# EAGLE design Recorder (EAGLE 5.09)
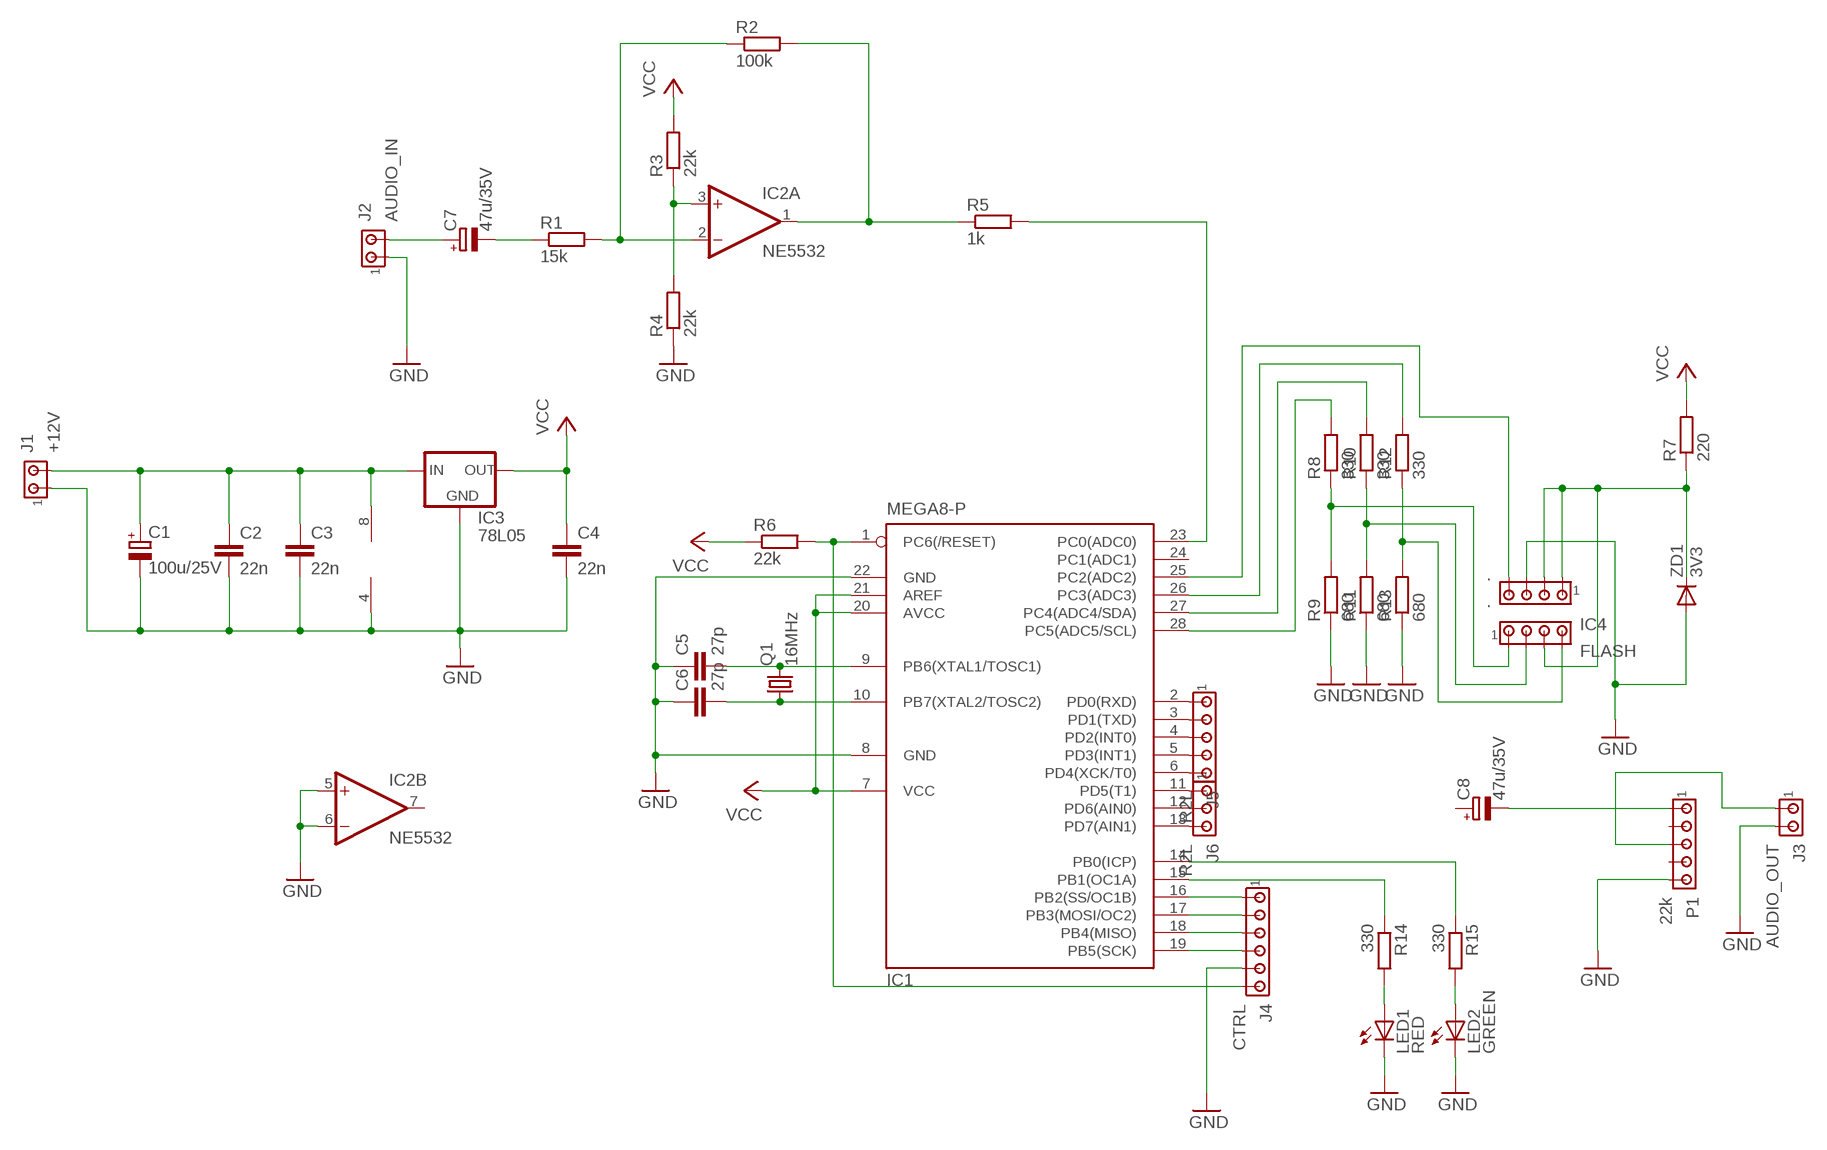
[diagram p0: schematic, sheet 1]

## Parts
.  .  MTA04-100  [10X04MTA]
C1  100u/25V  CPOL-EUE5-5  [E5-5]
C2  22n  C-EU025-024X044  [C025-024X044]
C3  22n  C-EU025-024X044  [C025-024X044]
C4  22n  C-EU025-024X044  [C025-024X044]
C5  27p  C-EU050-024X044  [C050-024X044]
C6  27p  C-EU050-024X044  [C050-024X044]
C7  47u/35V  CPOL-EUE2.5-5  [E2,5-5]
C8  47u/35V  CPOL-EUE2.5-5  [E2,5-5]
IC1  MEGA8-P  [DIL28-3]
IC2  NE5532  LM1458N  [DIL08]
IC3  78L05  78XXS  [78XXS]
IC4  FLASH  MTA04-100  [10X04MTA]
J1  +12V  MTA02-100  [10X02MTA]
J2  AUDIO_IN  MTA02-100  [10X02MTA]
J3  AUDIO_OUT  MTA02-100  [10X02MTA]
J4  CTRL  MTA06-100  [10X06MTA]
J5  R2L  MTA05-100  [10X05MTA]
J6  R2L  MTA03-100  [10X03MTA]
LED1  RED  LED5MM  [LED5MM]
LED2  GREEN  LED5MM  [LED5MM]
P1  22k  MTA05-100  [10X05MTA]
Q1  16MHz  CRYSTALHC49U-V  [HC49U-V]
R1  15k  R-EU_0207/10  [0207/10]
R2  100k  R-EU_0207/10  [0207/10]
R3  22k  R-EU_0207/10  [0207/10]
R4  22k  R-EU_0207/10  [0207/10]
R5  1k  R-EU_0207/2V  [0207/2V]
R6  22k  R-EU_0207/10  [0207/10]
R7  220  R-EU_0207/10  [0207/10]
R8  330  R-EU_0207/10  [0207/10]
R9  680  R-EU_0207/10  [0207/10]
R10  330  R-EU_0207/10  [0207/10]
R11  680  R-EU_0207/10  [0207/10]
R12  330  R-EU_0207/10  [0207/10]
R13  680  R-EU_0207/10  [0207/10]
R14  330  R-EU_0207/10  [0207/10]
R15  330  R-EU_0207/10  [0207/10]
ZD1  3V3  1N4148DO35-7  [DO35-7]

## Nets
GND: ..3 C1.- C2.2 C3.2 C4.2 C5.1 C6.1 IC1.8(GND) IC1.22(GND) IC2.4(P:V-) IC2.5(B:+IN) IC2.6(B:-IN) IC3.GND J1.1 J2.1 J3.2 J4.2 LED1.K(C) LED2.K(C) P1.5 R4.1 R9.1 R11.1 R13.1 ZD1.A
N$1: IC1.2(PD0(RXD)) J5.1
N$2: IC1.3(PD1(TXD)) J5.2
N$3: IC1.4(PD2(INT0)) J5.3
N$4: IC1.5(PD3(INT1)) J5.4
N$5: IC1.6(PD4(XCK/T0)) J5.5
N$6: IC1.11(PD5(T1)) J6.1
N$7: IC1.13(PD7(AIN1)) J6.3
N$8: IC1.12(PD6(AIN0)) J6.2
N$9: C5.2 IC1.9(PB6(XTAL1/TOSC1)) Q1.2
N$10: C6.2 IC1.10(PB7(XTAL2/TOSC2)) Q1.1
N$11: IC1.1(PC6(/RESET)) J4.1 R6.2
N$12: C8.- P1.1
N$13: J3.1 P1.3
N$14: IC2.2(A:-IN) R1.2 R2.1
N$15: IC1.23(PC0(ADC0)) R5.2
N$16: C7.- R1.1
N$17: C7.+ J2.2
N$18: IC2.3(A:+IN) R3.1 R4.2
N$19: IC2.1(A:OUT) R2.2 R5.1
N$20: LED1.A R14.2
N$21: LED2.A R15.2
N$22: IC1.15(PB1(OC1A)) R14.1
N$23: IC1.28(PC5(ADC5/SCL)) R8.2
N$24: IC1.14(PB0(ICP)) R15.1
N$25: IC4.1 R8.1 R9.2
N$27: ..1 ..2 IC4.3 R7.1 ZD1.C
N$28: IC4.2 R10.1 R11.2
N$29: IC1.17(PB3(MOSI/OC2)) J4.5
N$30: IC4.4 R12.1 R13.2
N$31: IC1.18(PB4(MISO)) J4.4
N$32: IC1.19(PB5(SCK)) J4.3
N$33: IC1.27(PC4(ADC4/SDA)) R10.2
N$34: IC1.16(PB2(SS/OC1B)) J4.6
N$35: ..4 IC1.25(PC2(ADC2))
N$36: C1.+ C2.1 C3.1 IC2.8(P:V+) IC3.IN J1.2
N$37: IC1.26(PC3(ADC3)) R12.2
VCC: C4.1 IC1.7(VCC) IC1.20(AVCC) IC1.21(AREF) IC3.OUT R3.2 R6.1 R7.2
Unconnected: C8.+ IC1.24(PC1(ADC1)) IC2.7(B:OUT) P1.2 P1.4

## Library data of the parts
. IC4 = con-amp:MTA04-100: AMP connector
C1 C7 C8 = rcl:CPOL-EU: POLARIZED CAPACITOR, European symbol
C2-C6 = rcl:C-EU: CAPACITOR, European symbol
IC1 = atmel:MEGA8-P: MICROCONTROLLER 8 Kbytes FLASH, 1 kbytes SRAM, 512 bytes EEPROM, USART, 4-channel 10 bit ADC, 2-channel 8 bit ADC Pin compatible with Atmega48, ATMega88, ATMega168 Source: avr.lbr
IC2 = linear:*1458: OP AMP
IC3 = v-reg:78XXS: VOLTAGE REGULATOR
J1-J3 = con-amp:MTA02-100: AMP connector
J4 = con-amp:MTA06-100: AMP connector
J5 P1 = con-amp:MTA05-100: AMP connector
J6 = con-amp:MTA03-100: AMP connector
LED1 LED2 = led:LED: LED
Q1 = crystal:CRYSTAL: CRYSTAL
R1-R15 = rcl:R-EU_: RESISTOR, European symbol
ZD1 = diode:1N4148: DIODE

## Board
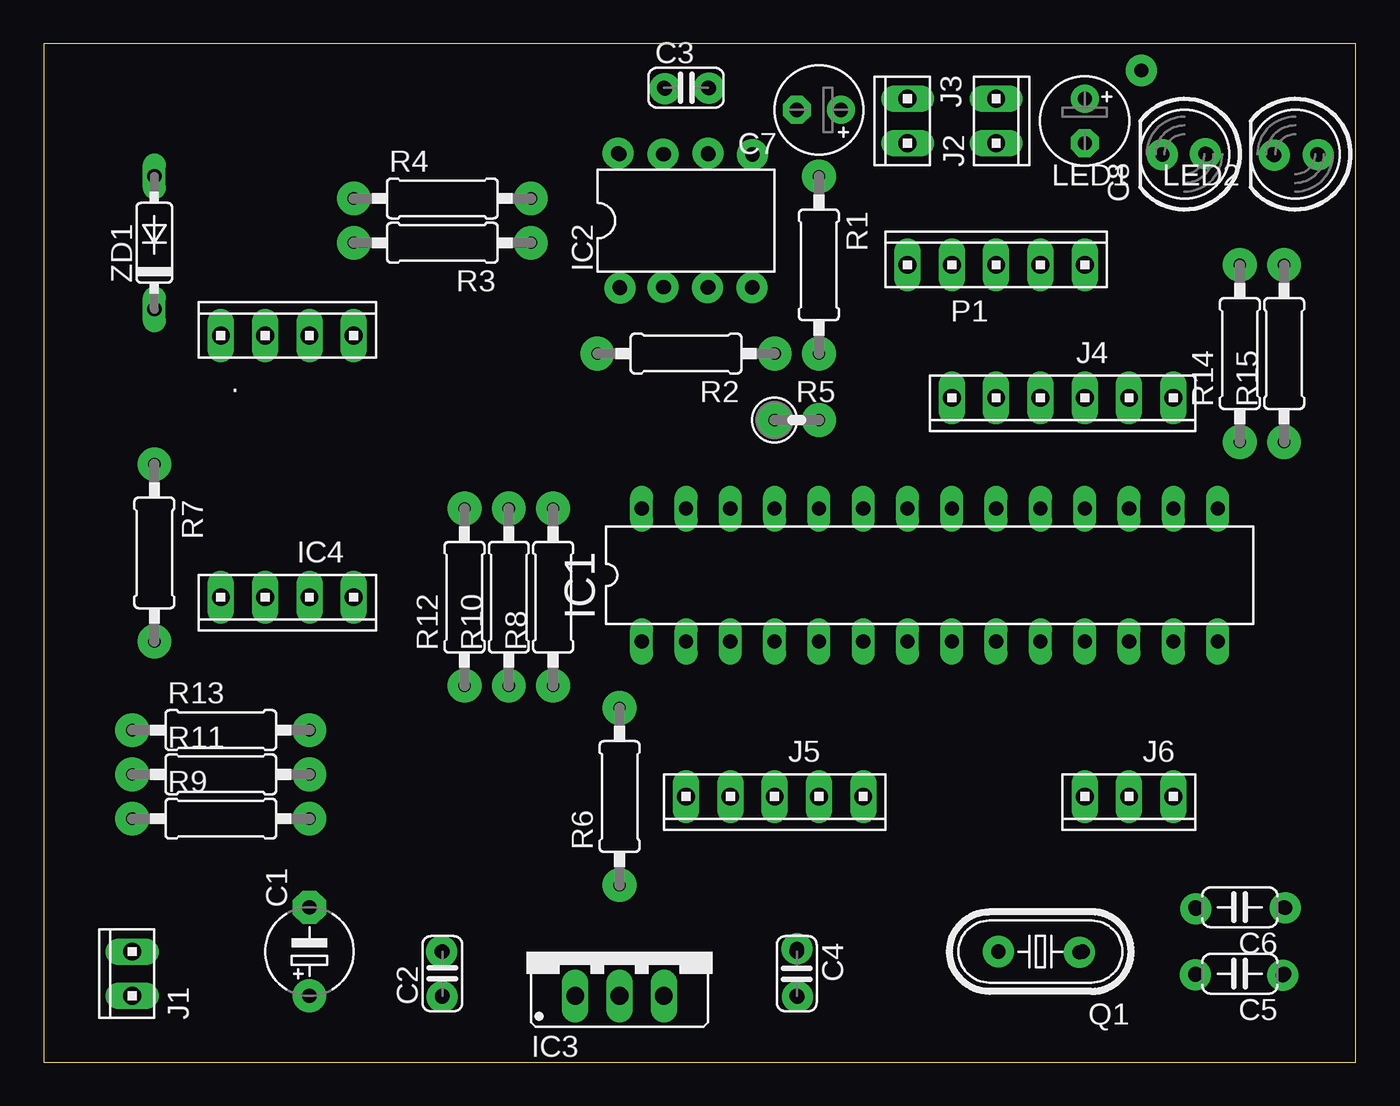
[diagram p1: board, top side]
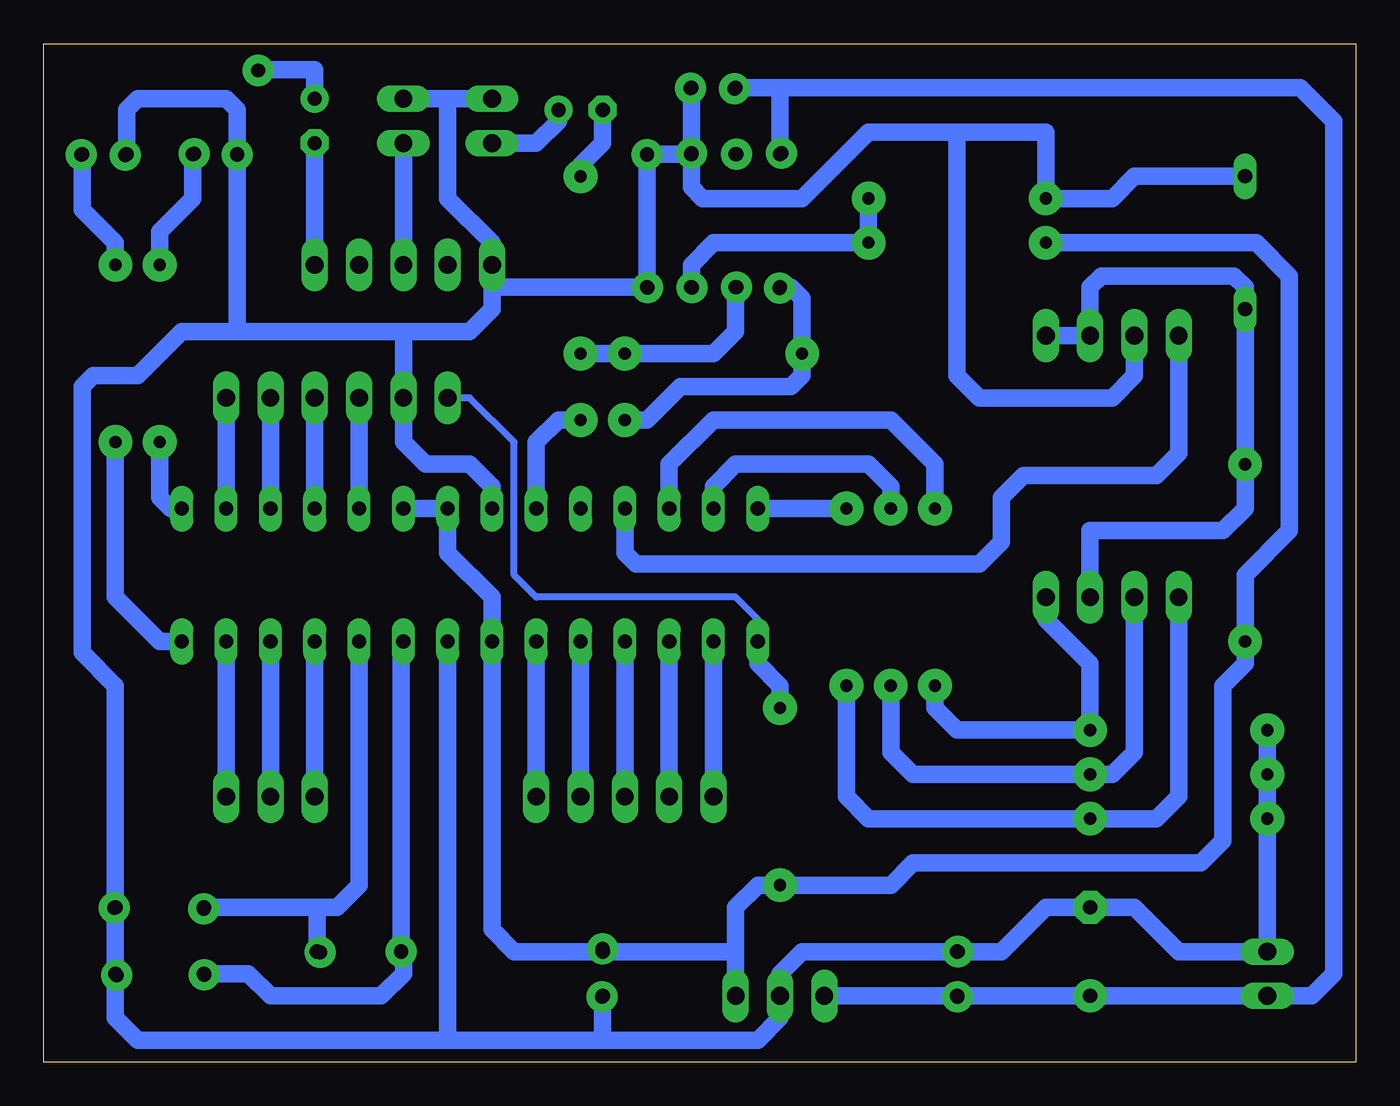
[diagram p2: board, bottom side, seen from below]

Size 75.23 x 58.41 mm. Coordinates in mm from the lower left corner, seen from the top.
Outline: 0,0 75.23,0 75.23,58.41 0,58.41 0,0
Copper layers (1*16): Top 0.035mm / dielectric 1.5mm / Bottom 0.035mm
Design rules "default": minimum track width 10mil, minimum drill 24mil, track to track 8mil, track to pad 8mil, pad to pad 8mil, via to via 8mil, smd to smd 8mil, copper to edge 40mil, drill to drill 8mil, minimum pad ring 10mil, minimum via ring 8mil, stop-mask expansion 4mil, vias tented up to drill 0mil, thermal gap 10mil

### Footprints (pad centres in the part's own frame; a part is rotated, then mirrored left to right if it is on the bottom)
10X04MTA = drill 1.016 long: 1 3.81,0; 2 1.27,0; 3 -1.27,0; 4 -3.81,0
E5-5 = drill 0.813 pad 1.905 round: + -2.54,0 | drill 0.813 pad 1.905 octagon: - 2.54,0
C025-024X044 = drill 0.813 octagon: 1 -1.27,0; 2 1.27,0
C050-024X044 = drill 0.813 octagon: 1 -2.54,0; 2 2.54,0
E2,5-5 = drill 0.813 pad 1.6 round: + -1.27,0 | drill 0.813 pad 1.6 octagon: - 1.27,0
DIL28-3 = drill 0.813 long: 1 -16.51,-3.81; 2 -13.97,-3.81; 3 -11.43,-3.81; 4 -8.89,-3.81; 5 -6.35,-3.81; 6 -3.81,-3.81; 7 -1.27,-3.81; 8 1.27,-3.81; 9 3.81,-3.81; 10 6.35,-3.81; 11 8.89,-3.81; 12 11.43,-3.81; 13 13.97,-3.81; 14 16.51,-3.81; 15 16.51,3.81; 16 13.97,3.81; 17 11.43,3.81; 18 8.89,3.81; 19 6.35,3.81; 20 3.81,3.81; 21 1.27,3.81; 22 -1.27,3.81; 23 -3.81,3.81; 24 -6.35,3.81; 25 -8.89,3.81; 26 -11.43,3.81; 27 -13.97,3.81; 28 -16.51,3.81
DIL08 = drill 0.813 pad 1.27 round: 1 -3.81,-3.81; 2 -1.27,-3.81; 3 1.27,-3.81; 4 3.81,-3.81; 5 3.81,3.81; 6 1.27,3.81; 7 -1.27,3.81; 8 -3.81,3.81
78XXS = drill 1.016 long: GND 0,-2.54; IN -2.54,-2.54; OUT 2.54,-2.54
10X02MTA = drill 1.016 long: 1 1.27,0; 2 -1.27,0
10X06MTA = drill 1.016 long: 1 6.35,0; 2 3.81,0; 3 1.27,0; 4 -1.27,0; 5 -3.81,0; 6 -6.35,0
10X05MTA = drill 1.016 long: 1 5.08,0; 2 2.54,0; 3 0,0; 4 -2.54,0; 5 -5.08,0
10X03MTA = drill 1.016 long: 1 2.54,0; 2 0,0; 3 -2.54,0
LED5MM = drill 0.813 octagon: A -1.27,0; K 1.27,0
HC49U-V = drill 0.813 round: 1 -2.413,0; 2 2.413,0
0207/10 = drill 0.7 pad 1.93 round: 1 -5.08,0; 2 5.08,0
0207/2V = drill 0.7 pad 1.93 round: 1 -1.27,0; 2 1.27,0
DO35-7 = drill 0.813 long: A 3.81,0; C -3.81,0

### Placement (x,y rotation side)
.  13.97,41.67 0 top
C1  15.24,6.35 90 top
C2  22.86,5.08 90 top
C3  36.83,55.88 0 top
C4  43.18,5.08 270 top
C5  68.58,5.08 180 top
C6  68.58,8.89 180 top
C7  44.45,54.61 180 top
C8  59.69,53.98 270 top
IC1  50.8,27.94 0 top
IC2  36.83,48.26 0 top
IC3  33.02,6.35 0 top
IC4  13.97,26.67 180 top
J1  5.08,5.08 90 top
J2  49.53,53.98 90 top
J3  54.61,53.98 270 top
J4  58.42,38.1 180 top
J5  41.91,15.24 180 top
J6  62.23,15.24 180 top
LED1  65.41,52.07 180 top
LED2  71.75,52.07 180 top
P1  54.61,45.72 0 top
Q1  57.15,6.35 180 top
R1  44.45,45.72 270 top
R2  36.83,40.64 180 top
R3  22.86,46.99 180 top
R4  22.86,49.53 0 top
R5  43.18,36.83 0 top
R6  33.02,15.24 90 top
R7  6.35,29.21 270 top
R8  29.21,26.67 90 top
R9  10.16,13.97 0 top
R10  26.67,26.67 90 top
R11  10.16,16.51 0 top
R12  24.13,26.67 90 top
R13  10.16,19.05 0 top
R14  68.58,40.64 90 top
R15  71.12,40.64 90 top
ZD1  6.35,46.99 90 top

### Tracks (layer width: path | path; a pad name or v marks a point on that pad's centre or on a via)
GND  (via drill 0.8 pad 1.78)
  Bottom 1.016: 43.18,1.27 34.29,1.27 33.02,2.54 IC3.GND 33.02,5.08 31.75,6.35 C2.2 v22.81,6.35 20.32,6.35 17.78,8.89 C1.- 12.7,8.89 10.16,6.35 J1.1 R9.1 R11.1 R13.1 | 43.18,1.27 52.07,1.27 | 52.07,1.27 IC1.8 | 43.18,1.27 C4.2 | IC1.22 49.53,33.02 50.8,34.29 53.34,34.29 54.61,35.56 J4.2 54.61,41.91 | 52.07,1.27 69.85,1.27 71.12,2.54 C5.1 C6.1 71.12,21.59 73.03,23.49 73.03,38.73 72.39,39.37 69.85,39.37 67.31,41.91 64.14,41.91 | IC2.6 IC2.5 IC2.4 49.53,44.45 | IC2.6 C3.2 | 22.86,53.34 17.78,53.34 R4.1 13.97,49.53 12.7,50.8 ZD1.A | 22.86,53.34 27.94,53.34 31.75,49.53 37.47,49.53 38.1,50.16 IC2.6 | ..3 12.7,39.37 13.97,38.1 21.59,38.1 22.86,39.37 22.86,53.34 | 52.07,55.24 J2.1 | 52.07,55.24 J3.2 | 52.07,55.24 52.07,49.53 49.53,46.99 P1.5 49.53,44.45 | 54.61,41.91 50.8,41.91 49.53,43.18 49.53,44.45 | 64.14,41.91 54.61,41.91 | LED2.K 70.48,54.61 69.85,55.24 64.77,55.24 64.14,54.61 LED1.K 64.14,41.91
N$1
  Bottom 1.016: J5.1 IC1.2
N$2
  Bottom 1.016: IC1.3 J5.2
N$3
  Bottom 1.016: J5.3 IC1.4
N$4
  Bottom 1.016: IC1.5 J5.4
N$5
  Bottom 1.016: J5.5 IC1.6
N$6
  Bottom 1.016: IC1.11 J6.1
N$7
  Bottom 1.016: IC1.13 J6.3
N$8
  Bottom 1.016: J6.2 IC1.12
N$9
  Bottom 1.016: C5.2 63.5,5.08 62.23,3.81 55.88,3.81 54.61,5.08 54.61,6.22 Q1.2 54.74,24 IC1.9
N$10
  Bottom 1.016: 59.69,8.89 58.42,8.89 57.15,10.16 IC1.10 | 59.69,8.89 C6.2 | Q1.1 59.56,8.76 59.69,8.89
N$11
  Bottom 0.406: IC1.1 34.29,25.4 35.56,26.67 46.99,26.67 48.26,27.94 48.26,35.56 50.8,38.1 J4.1
  Bottom 1.016: IC1.1 34.29,22.86 33.02,21.59 R6.2
N$12
  Bottom 1.016: P1.1 C8.-
N$13
  Bottom 1.016: J3.1 P1.3
N$14
  Bottom 1.016: R1.2 R2.1 36.83,40.64 35.56,41.91 IC2.2
N$15
  Bottom 1.016: R5.2 45.72,36.83 46.99,35.56 IC1.23
N$16
  Bottom 1.016: C7.- 43.18,52.7 44.45,51.43 R1.1
N$17
  Bottom 1.016: C7.+ 45.72,53.98 46.99,52.7 J2.2
N$18
  Bottom 1.016: R4.2 R3.1 36.83,46.99 38.1,45.72 IC2.3
N$19
  Bottom 1.016: R5.1 40.64,36.83 38.73,38.73 32.38,38.73 31.75,39.37 R2.2 31.75,43.81 32.38,44.45 IC2.1
N$20
  Bottom 1.016: R14.2 68.58,47.62 66.67,49.53 LED1.A
N$21
  Bottom 1.016: R15.2 71.12,46.99 73.03,48.9 LED2.A
N$22
  Bottom 1.016: IC1.15 67.94,31.75 68.58,32.38 R14.1
N$23
  Bottom 1.016: R8.2 IC1.28
N$24
  Bottom 1.016: IC1.14 68.58,24.13 71.12,26.67 R15.1
N$25
  Bottom 1.016: R8.1 29.21,15.24 27.94,13.97 R9.2 11.43,13.97 10.16,15.24 IC4.1
N$26  (via drill 0.8 pad 1.78)
  other vias: 22.84,3.76
N$27
  Bottom 1.016: IC4.3 15.24,30.48 7.62,30.48 6.35,31.75 R7.1 ZD1.C 6.35,44.45 6.99,45.09 14.61,45.09 15.24,44.45 ..2 ..1
N$28
  Bottom 1.016: R10.1 26.67,17.78 25.4,16.51 R11.2 13.97,16.51 12.7,17.78 IC4.2
N$29
  Bottom 1.016: J4.5 IC1.17
N$30
  Bottom 1.016: R12.1 24.13,20.32 22.86,19.05 R13.2 15.24,22.86 17.78,25.4 IC4.4
N$31
  Bottom 1.016: IC1.18 J4.4
N$32
  Bottom 1.016: J4.3 IC1.19
N$33
  Bottom 1.016: R10.2 26.67,33.02 27.94,34.29 35.56,34.29 36.83,33.02 IC1.27
N$34
  Bottom 1.016: IC1.16 J4.6
N$35
  Bottom 1.016: IC1.25 41.91,29.21 41.27,28.57 21.59,28.57 20.32,29.84 20.32,32.38 19.05,33.66 11.43,33.66 10.16,34.92 ..4
N$36
  Bottom 1.016: IC3.IN C2.1 C1.+ J1.2 2.54,3.81 1.27,5.08 1.27,53.98 3.17,55.88 33.02,55.88 | 33.02,55.88 IC2.8 | 33.02,55.88 C3.1
N$37
  Bottom 1.016: R12.2 24.13,34.29 26.67,36.83 36.83,36.83 39.37,34.29 IC1.26
N$38  (via drill 0.8 pad 1.78)
  other vias: 43.19,6.5
N$39  (via drill 0.8 pad 1.78)
  other vias: 43.23,3.75
N$40  (via drill 0.8 pad 1.78)
  other vias: 54.75,6.35
N$41  (via drill 0.8 pad 1.78)
  other vias: 59.39,6.32
N$42  (via drill 0.8 pad 1.78)
  other vias: 66.07,8.8
N$43  (via drill 0.8 pad 1.78)
  other vias: 71.2,8.87
N$44  (via drill 0.8 pad 1.78)
  other vias: 66.04,5.03
N$45  (via drill 0.8 pad 1.78)
  other vias: 71.04,4.99
N$46  (via drill 0.8 pad 1.78)
  other vias: 64.14,52.03
N$47  (via drill 0.8 pad 1.78)
  other vias: 66.59,52.1
N$48  (via drill 0.8 pad 1.78)
  other vias: 70.55,52.01
N$49  (via drill 0.8 pad 1.78)
  other vias: 73.08,52.05
N$50  (via drill 0.8 pad 1.78)
  other vias: 32.93,52.13
N$51  (via drill 0.8 pad 1.78)
  other vias: 35.52,52.07
N$52  (via drill 0.8 pad 1.78)
  other vias: 38.09,52.13
N$53  (via drill 0.8 pad 1.78)
  other vias: 40.63,52.04
N$54  (via drill 0.8 pad 1.78)
  other vias: 33.06,44.4
N$55  (via drill 0.8 pad 1.78)
  other vias: 35.51,44.44
N$56  (via drill 0.8 pad 1.78)
  other vias: 38.07,44.43
N$57  (via drill 0.8 pad 1.78)
  other vias: 40.6,44.43
N$58  (via drill 0.8 pad 1.78)
  other vias: 35.62,55.82
N$59  (via drill 0.8 pad 1.78)
  other vias: 38.14,55.85
N$60  (via drill 0.8 pad 1.78)
  other vias: 62.93,56.87
N$61
  Bottom 1.016: 63.05,56.91 59.71,56.91 59.71,55.19
VCC
  Bottom 1.016: 35.56,6.35 35.56,8.89 34.29,10.16 R6.1 26.67,10.16 25.4,11.43 8.89,11.43 7.62,12.7 7.62,21.59 6.35,22.86 R7.2 6.35,27.94 3.81,30.48 3.81,45.09 5.71,46.99 R3.2 | 35.56,6.35 IC3.OUT | 35.56,6.35 C4.1 48.26,6.35 49.53,7.62 IC1.7 49.53,26.67 52.07,29.21 IC1.21 IC1.20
